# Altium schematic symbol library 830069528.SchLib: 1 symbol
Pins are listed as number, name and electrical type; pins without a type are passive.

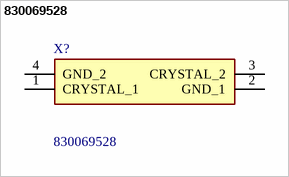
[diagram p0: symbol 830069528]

## 830069528
designator X?
Crystals WE-XTAL 48.0MHz 15ppm 1.6 x 1.2mm; Manufacturer_Name: Wurth Elektronik; Geometry.Height: 0.4mm
footprint 830069528
pins: 1 CRYSTAL_1, 2 GND_1, 3 CRYSTAL_2, 4 GND_2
